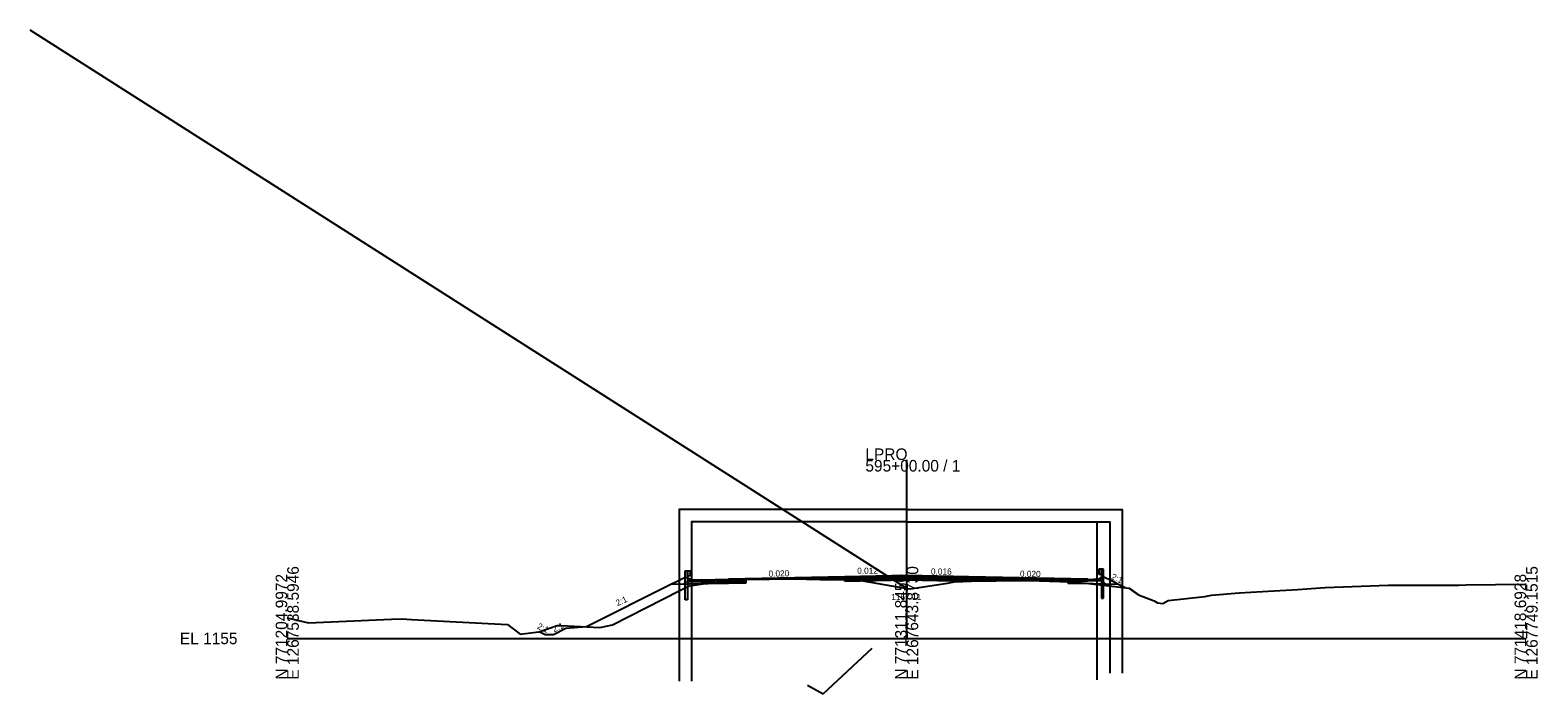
# Model space of a CAD drawing. Extents: x -3833 to 1267678, y -522 to 773248.
# Drawn here: x -62.2 to 302.8, y 5986.6 to 6147.2 of the extents above; entities that cross this region are included whole.
import ezdxf

# ---------------------------------------------------------------- set-up
doc = ezdxf.new("R2010")
doc.units = 0
for name, color, linetype in [('Exist Cross Section Cell', 7, 'Continuous'), ('Exist XS Center Line Elevation Label', 7, 'Continuous'), ('Exist XS Ground Line', 7, 'Continuous'), ('Prop CMT DNC', 7, 'Continuous'), ('Prop CMT Guardrail Graphics', 7, 'Continuous'), ('Prop CMT Pvmt Course 1', 7, 'Continuous'), ('Prop CMT Pvmt Course 2', 7, 'Continuous'), ('Prop CMT Pvmt Course 4', 7, 'Continuous'), ('Prop CMT Shld Paved Course 1', 7, 'Continuous'), ('Prop CMT Shld Paved Course 2', 7, 'Continuous'), ('Prop CMT Shld Paved Course 4', 7, 'Continuous'), ('Prop CMT Slope Grass', 7, 'Continuous'), ('Prop CMT Subgrade Earthwork', 7, 'Continuous'), ('Prop Corridor Mesh Bottom', 7, 'Continuous'), ('Prop XS Ditch Slope Text', 7, 'Continuous'), ('Prop XS Finish Grade', 7, 'Continuous'), ('Prop XS Label Text', 7, 'Continuous'), ('Prop XS SE Text', 7, 'Continuous'), ('Scratch_Level_1', 7, 'Continuous'), ('Scratch_Level_5', 7, 'Continuous'), ('Typical Curb CELL', 7, 'Continuous')]:
    doc.layers.add(name, color=color, linetype=linetype)

msp = doc.modelspace()

# ---------------------------------------------------------------- linework, layer by layer
at = {"layer": 'Exist Cross Section Cell'}
for p, q in [((150, 6000), (150, 6043.17)), ((0, 6000), (150, 6000)), ((150, 6000), (300, 6000))]:
    msp.add_line(p, q, dxfattribs=at)
at = {"layer": 'Exist XS Ground Line'}
for p, q in [((97.99, 6012.77), (106.25, 6013.98)), ((106.25, 6013.98), (108.66, 6014.13)), ((108.66, 6014.13), (111.05, 6014.3)), ((108.66, 6014.13), (111.05, 6014.3)), ((111.05, 6014.3), (116.77, 6014.34)), ((111.05, 6014.3), (116.77, 6014.34)), ((116.77, 6014.34), (122.39, 6014.39)), ((116.77, 6014.34), (122.39, 6014.39)), ((122.39, 6014.39), (129.02, 6014.27)), ((122.39, 6014.39), (129.02, 6014.27)), ((129.02, 6014.27), (136.17, 6014.14)), ((129.02, 6014.27), (136.17, 6014.14)), ((136.17, 6014.14), (137.39, 6014.09)), ((136.17, 6014.14), (137.39, 6014.09)), ((137.39, 6014.09), (138.63, 6014.02)), ((137.39, 6014.09), (138.63, 6014.02)), ((138.63, 6014.02), (139.36, 6013.96)), ((138.63, 6014.02), (139.36, 6013.96)), ((139.36, 6013.96), (150, 6012.11)), ((139.36, 6013.96), (150, 6012.11)), ((150.83, 6011.96), (159.85, 6013.35)), ((150.83, 6011.96), (159.85, 6013.35)), ((159.85, 6013.35), (160.7, 6013.49)), ((159.85, 6013.35), (160.7, 6013.49)), ((160.7, 6013.49), (161.61, 6013.67)), ((160.7, 6013.49), (161.61, 6013.67)), ((161.61, 6013.67), (165.61, 6013.84)), ((161.61, 6013.67), (165.61, 6013.84)), ((165.61, 6013.84), (177.73, 6014.03)), ((165.61, 6013.84), (177.73, 6014.03)), ((177.73, 6014.03), (179.64, 6013.98)), ((177.73, 6014.03), (179.64, 6013.98)), ((179.64, 6013.98), (189.48, 6013.71)), ((179.64, 6013.98), (189.48, 6013.71)), ((189.48, 6013.71), (193.42, 6013.4)), ((193.42, 6013.4), (203.88, 6012.13)), ((193.42, 6013.4), (203.88, 6012.13)), ((285.5, 6012.96), (292.56, 6013.03)), ((292.56, 6013.03), (300, 6013.08)), ((78.73, 6003.26), (95.07, 6011.55)), ((78.73, 6003.26), (95.07, 6011.55)), ((95.07, 6011.55), (97.16, 6012.67)), ((95.07, 6011.55), (97.16, 6012.67)), ((97.16, 6012.67), (97.99, 6012.77)), ((150, 6012.11), (150.83, 6011.96)), ((150, 6012.11), (150.83, 6011.96)), ((203.87, 6012.09), (206.15, 6010.47)), ((203.88, 6012.13), (206.16, 6010.51)), ((206.16, 6010.51), (209.91, 6009.06)), ((206.16, 6010.51), (209.91, 6009.06)), ((213.31, 6009.13), (222.19, 6010.14)), ((213.31, 6009.13), (222.19, 6010.14)), ((222.19, 6010.14), (223.85, 6010.44)), ((222.19, 6010.14), (223.85, 6010.44)), ((223.85, 6010.44), (230.49, 6011.04)), ((223.85, 6010.44), (230.49, 6011.04)), ((230.49, 6011.04), (244.64, 6011.79)), ((230.49, 6011.04), (244.64, 6011.79)), ((244.64, 6011.79), (251.33, 6012.28)), ((244.64, 6011.79), (251.33, 6012.28)), ((251.33, 6012.28), (266.61, 6012.88)), ((266.61, 6012.88), (283.6, 6012.88)), ((283.6, 6012.88), (285.5, 6012.96)), ((209.91, 6009.06), (210.72, 6008.63)), ((209.91, 6009.06), (210.72, 6008.63)), ((210.72, 6008.63), (211.99, 6008.42)), ((210.72, 6008.63), (211.99, 6008.42)), ((211.99, 6008.42), (213.31, 6009.13)), ((211.99, 6008.42), (213.31, 6009.13)), ((0, 6004.94), (5.16, 6003.79)), ((5.16, 6003.79), (25.23, 6004.67)), ((25.23, 6004.67), (27.81, 6004.76)), ((27.81, 6004.76), (30.1, 6004.6)), ((30.1, 6004.6), (53.33, 6003.38)), ((53.33, 6003.38), (56.43, 6001.03)), ((53.33, 6003.38), (56.43, 6001.03)), ((60.91, 6001.55), (65.38, 6003.09)), ((60.91, 6001.55), (65.38, 6003.09)), ((65.38, 6003.09), (66.32, 6003.13)), ((65.38, 6003.09), (66.32, 6003.13)), ((66.32, 6003.13), (75.69, 6002.6)), ((66.32, 6003.13), (75.69, 6002.6)), ((75.69, 6002.6), (78.73, 6003.26)), ((75.69, 6002.6), (78.73, 6003.26)), ((56.43, 6001.03), (60.91, 6001.55)), ((56.43, 6001.03), (60.91, 6001.55))]:
    msp.add_line(p, q, dxfattribs=at)
at = {"layer": 'Prop CMT Guardrail Graphics'}
for p, q in [((196.53, 6016.73), (196.53, 6015.54)), ((197.2, 6016.73), (196.53, 6016.73)), ((197.2, 6016.73), (197.2, 6014.21)), ((197.68, 6016.73), (197.2, 6016.73)), ((197.2, 6015.54), (197.2, 6016.73)), ((197.68, 6014.22), (197.68, 6016.73)), ((96.4, 6013.85), (96.4, 6016.35)), ((96.4, 6016.35), (96.89, 6016.35)), ((96.4, 6009.34), (96.4, 6013.85)), ((96.89, 6016.35), (96.89, 6013.84)), ((96.89, 6015.17), (96.89, 6016.35)), ((96.89, 6016.35), (97.55, 6016.35)), ((97.55, 6015.17), (96.89, 6015.17)), ((96.89, 6013.84), (96.89, 6009.34)), ((97.55, 6016.35), (97.55, 6015.17)), ((97.55, 6016.27), (97.55, 6015.25)), ((97.65, 6016.25), (97.55, 6016.27)), ((97.55, 6015.25), (97.65, 6015.27)), ((97.57, 6015.8), (97.8, 6016)), ((97.57, 6015.71), (97.57, 6015.8)), ((97.8, 6015.51), (97.57, 6015.71)), ((97.8, 6016.15), (97.65, 6016.25)), ((97.65, 6015.27), (97.8, 6015.37)), ((97.8, 6016), (97.8, 6016.15)), ((97.8, 6015.37), (97.8, 6015.51)), ((196.29, 6016.52), (196.43, 6016.62)), ((196.29, 6016.38), (196.29, 6016.52)), ((196.52, 6016.18), (196.29, 6016.38)), ((196.29, 6015.89), (196.52, 6016.09)), ((196.29, 6015.74), (196.29, 6015.89)), ((196.43, 6015.64), (196.29, 6015.74)), ((196.43, 6016.62), (196.53, 6016.65)), ((196.53, 6015.62), (196.43, 6015.64)), ((196.52, 6016.09), (196.52, 6016.18)), ((196.53, 6016.65), (196.53, 6015.62)), ((196.53, 6015.54), (197.2, 6015.54)), ((197.2, 6014.21), (197.2, 6009.71)), ((197.68, 6009.71), (197.68, 6014.22)), ((197.2, 6009.71), (197.68, 6009.71)), ((96.89, 6009.34), (96.4, 6009.34))]:
    msp.add_line(p, q, dxfattribs=at)
at = {"layer": 'Prop CMT Pvmt Course 1'}
for p, q in [((135, 6014.9), (106.89, 6014.34)), ((106.89, 6014.34), (106.89, 6014.34)), ((106.89, 6014.34), (106.89, 6014.09)), ((106.89, 6014.09), (111.05, 6014.17)), ((106.89, 6014.09), (106.89, 6014.09)), ((111.05, 6014.3), (135, 6014.65)), ((135, 6014.65), (135, 6014.9)), ((135, 6014.65), (135, 6014.65)), ((193.84, 6014.32), (165, 6014.9)), ((165, 6014.9), (165, 6014.65)), ((165, 6014.65), (165, 6014.65)), ((165, 6014.65), (193.84, 6014.07)), ((189, 6014.17), (189, 6014.42)), ((189, 6014.42), (193.84, 6014.32)), ((195.16, 6014.01), (195.16, 6014.01))]:
    msp.add_line(p, q, dxfattribs=at)
at = {"layer": 'Prop CMT Pvmt Course 2'}
for p, q in [((150, 6014.95), (135, 6014.65)), ((135, 6014.65), (135, 6014.65)), ((135, 6014.65), (135, 6014.32)), ((135, 6014.32), (150, 6014.62)), ((135, 6014.32), (135, 6014.32)), ((135, 6014.32), (135, 6014.32)), ((135, 6014.32), (135, 6014.32)), ((165, 6014.65), (150, 6014.95)), ((150, 6014.62), (165, 6014.32)), ((165, 6014.32), (165, 6014.65)), ((165, 6014.65), (165, 6014.65)), ((165, 6014.32), (165, 6014.32)), ((165, 6014.32), (165, 6014.32)), ((165, 6014.32), (165, 6014.32))]:
    msp.add_line(p, q, dxfattribs=at)
at = {"layer": 'Prop CMT Pvmt Course 4'}
for p, q in [((135, 6014.32), (130.86, 6014.23)), ((130.86, 6014.23), (130.95, 6014.24)), ((130.86, 6014.23), (130.86, 6014.23)), ((130.95, 6014.24), (135, 6014.16)), ((150, 6014.62), (135, 6014.32)), ((135, 6014.16), (135, 6014.32)), ((135, 6014.32), (135, 6014.32)), ((135, 6014.32), (135, 6014.32)), ((135, 6014.32), (135, 6014.32)), ((135, 6014.32), (135, 6014.32)), ((135, 6014.32), (135.01, 6013.87)), ((135, 6014.16), (135, 6014.16)), ((135, 6014.16), (135, 6014.16)), ((135, 6014.16), (135, 6014.16)), ((135.01, 6013.86), (150, 6014.16)), ((135.01, 6013.87), (135.01, 6013.87)), ((135.01, 6013.87), (135.01, 6013.86)), ((135.01, 6013.86), (135.01, 6013.86)), ((135.01, 6013.86), (135.01, 6013.86)), ((165, 6014.32), (150, 6014.62)), ((150, 6014.16), (165, 6013.86)), ((165, 6013.86), (165, 6014.32)), ((165, 6014.32), (165, 6014.32)), ((165, 6014.32), (165, 6014.32)), ((165, 6013.81), (165, 6014.32)), ((165, 6014.32), (165, 6014.32)), ((165, 6014.32), (165, 6014.32)), ((165, 6013.86), (165, 6013.86)), ((165, 6013.86), (165, 6013.86)), ((165, 6013.86), (165, 6013.86)), ((165.61, 6013.84), (165, 6013.81)), ((165, 6013.81), (165, 6013.81)), ((165, 6013.81), (165, 6013.81)), ((165, 6013.81), (165, 6013.81)), ((166.15, 6013.85), (165.61, 6013.84)), ((173.29, 6013.96), (166.15, 6013.85)), ((177.73, 6014.03), (173.29, 6013.96)), ((179.44, 6013.99), (177.73, 6014.03)), ((182.31, 6013.91), (179.44, 6013.99)), ((187.82, 6013.76), (182.31, 6013.91)), ((189, 6013.73), (187.82, 6013.76)), ((189, 6013.84), (189, 6013.73))]:
    msp.add_line(p, q, dxfattribs=at)
at = {"layer": 'Prop CMT Shld Paved Course 1'}
for p, q in [((97.63, 6013.87), (97.63, 6013.87)), ((97.63, 6013.87), (97.63, 6013.87)), ((97.63, 6013.87), (97.63, 6013.87)), ((97.63, 6013.87), (97.63, 6013.87)), ((97.89, 6014.12), (97.89, 6014.12)), ((97.89, 6014.12), (97.89, 6014.12)), ((100.22, 6014.2), (106.89, 6014.34)), ((106.89, 6014.09), (100.22, 6013.95)), ((106.89, 6014.34), (106.89, 6014.09)), ((106.89, 6014.09), (106.89, 6014.09)), ((150, 6015.2), (135, 6014.9)), ((135, 6014.65), (150, 6014.95)), ((135, 6014.9), (135, 6014.9)), ((135, 6014.9), (135, 6014.65)), ((135, 6014.65), (135, 6014.65)), ((135, 6014.65), (135, 6014.65)), ((165, 6014.9), (150, 6015.2)), ((150, 6014.95), (165, 6014.65)), ((165, 6014.65), (165, 6014.9)), ((165, 6014.9), (165, 6014.9)), ((165, 6014.65), (165, 6014.65)), ((165, 6014.65), (165, 6014.65)), ((189, 6014.17), (189, 6014.17)), ((189, 6014.17), (193.84, 6014.07)), ((196.16, 6014.24), (195.16, 6014.26))]:
    msp.add_line(p, q, dxfattribs=at)
at = {"layer": 'Prop CMT Shld Paved Course 2'}
for p, q in [((97.29, 6013.53), (97.29, 6013.53)), ((97.29, 6013.53), (97.29, 6013.53)), ((97.29, 6013.53), (97.29, 6013.53)), ((97.29, 6013.53), (97.29, 6013.53)), ((97.63, 6013.87), (97.63, 6013.87)), ((97.63, 6013.87), (97.63, 6013.87)), ((106.89, 6014.09), (106.89, 6013.75)), ((106.89, 6013.75), (106.89, 6013.75)), ((111.05, 6014.3), (120.07, 6014.43)), ((111.05, 6014.3), (111.05, 6014.3)), ((120.07, 6014.43), (128.15, 6014.54)), ((129.02, 6014.27), (122.39, 6014.39)), ((128.15, 6014.54), (128.65, 6014.56)), ((128.65, 6014.56), (129.85, 6014.57)), ((130.86, 6014.23), (129.02, 6014.27)), ((129.02, 6014.27), (129.02, 6014.27)), ((129.85, 6014.57), (135, 6014.65)), ((135, 6014.32), (130.86, 6014.23)), ((130.86, 6014.23), (130.86, 6014.23)), ((135, 6014.65), (135, 6014.65)), ((135, 6014.65), (135, 6014.32)), ((135, 6014.32), (135, 6014.32)), ((135, 6014.32), (135, 6014.32)), ((165, 6014.32), (165, 6014.65)), ((165, 6014.65), (165, 6014.65)), ((165, 6014.65), (165.61, 6014.64)), ((165.61, 6014.3), (165, 6014.32)), ((165, 6014.32), (165, 6014.32)), ((165, 6014.32), (165, 6014.32)), ((165.61, 6014.64), (165.86, 6014.63)), ((165.86, 6014.3), (165.61, 6014.3)), ((165.86, 6014.63), (165.86, 6014.63)), ((165.86, 6014.63), (177.73, 6014.4)), ((177.73, 6014.06), (165.86, 6014.3)), ((165.86, 6014.3), (165.86, 6014.3)), ((177.73, 6014.4), (177.73, 6014.4)), ((177.73, 6014.4), (179.64, 6014.36)), ((179.64, 6014.02), (177.73, 6014.06)), ((177.73, 6014.06), (177.73, 6014.06)), ((179.64, 6014.36), (189, 6014.17)), ((179.64, 6014.36), (179.64, 6014.36)), ((189, 6013.84), (179.64, 6014.02)), ((179.64, 6014.02), (179.64, 6014.02)), ((189, 6014.17), (189, 6013.84))]:
    msp.add_line(p, q, dxfattribs=at)
at = {"layer": 'Prop CMT Shld Paved Course 4'}
for p, q in [((95.98, 6013.08), (96.69, 6013.79)), ((96.69, 6013.79), (97.2, 6013.79)), ((106.89, 6013.3), (96.82, 6013.09)), ((100.22, 6013.62), (111.05, 6013.84)), ((100.22, 6013.79), (100.22, 6013.62)), ((106.89, 6013.75), (106.89, 6013.3)), ((193.83, 6013.74), (189, 6013.84)), ((193.83, 6013.91), (193.83, 6013.74)), ((197.36, 6013.91), (196.85, 6013.91)), ((198.06, 6013.2), (197.36, 6013.91))]:
    msp.add_line(p, q, dxfattribs=at)
at = {"layer": 'Prop CMT Slope Grass'}
for p, q in [((94.59, 6013.86), (92.91, 6013.02)), ((96.5, 6014.81), (94.59, 6013.86)), ((96.5, 6014.81), (97.2, 6014.46)), ((197.61, 6014.96), (196.85, 6014.58)), ((197.61, 6014.96), (199.6, 6013.97)), ((199.6, 6013.97), (201.27, 6013.14))]:
    msp.add_line(p, q, dxfattribs=at)
at = {"layer": 'Prop CMT Subgrade Earthwork'}
for p, q in [((111.05, 6013.38), (92.91, 6013.02)), ((111.05, 6014.3), (111.05, 6013.38)), ((135.01, 6013.86), (135, 6014.16)), ((150, 6014.16), (135.01, 6013.86)), ((165, 6013.86), (150, 6014.16)), ((165, 6013.81), (165, 6013.86)), ((189, 6013.73), (189, 6013.38)), ((189, 6013.38), (195.17, 6013.26)), ((195.17, 6013.26), (201.27, 6013.14))]:
    msp.add_line(p, q, dxfattribs=at)
at = {"layer": 'Prop Corridor Mesh Bottom'}
for p, q in [((135, 6014.9), (135, 6014.65)), ((165, 6014.9), (165, 6014.65))]:
    msp.add_line(p, q, dxfattribs=at)
at = {"layer": 'Prop XS Finish Grade'}
for p, q in [((92.91, 6013.02), (72.44, 6002.78)), ((201.27, 6013.14), (203.09, 6012.23))]:
    msp.add_line(p, q, dxfattribs=at)
msp.add_lwpolyline([(72.44, 6002.78), (67.44, 6002.37), (64.44, 6000.87), (62.44, 6000.87), (61, 6001.59)], dxfattribs=at)
at = {"layer": 'Scratch_Level_1'}
msp.add_line((150, 6012.11), (-62.25, 6147.17), dxfattribs=at)
at = {"layer": 'Scratch_Level_5'}
for p, q in [((129.76, 5986.58), (141.61, 5997.61)), ((125.97, 5988.69), (129.76, 5986.58))]:
    msp.add_line(p, q, dxfattribs=at)
for points in [[(150, 6031.19), (94.89, 6031.19), (94.89, 5989.68)], [(150, 6028.19), (97.89, 6028.19), (97.89, 5989.68)], [(150, 6031.19), (202.17, 6031.19), (202.17, 5991.57)], [(150, 6028.19), (196.05, 6028.19), (196.05, 5990)], [(150, 6028.19), (199.17, 6028.19), (199.17, 5991.57)]]:
    msp.add_lwpolyline(points, dxfattribs=at)
at = {"layer": 'Typical Curb CELL'}
for p, q in [((97.2, 6013.79), (97.2, 6014.46)), ((97.89, 6014.12), (97.2, 6014.46)), ((97.2, 6013.79), (100.22, 6013.79)), ((97.23, 6014.09), (97.39, 6014.13)), ((97.37, 6014.04), (97.23, 6014.09)), ((97.39, 6014.13), (97.37, 6014.04)), ((97.9, 6014), (97.8, 6013.93)), ((97.8, 6013.93), (97.97, 6013.89)), ((100.21, 6014.2), (97.89, 6014.12)), ((97.97, 6013.89), (97.9, 6014)), ((98.65, 6014.06), (98.61, 6013.95)), ((98.61, 6013.95), (98.73, 6013.94)), ((98.73, 6013.94), (98.65, 6014.06)), ((99.15, 6014), (99.05, 6013.93)), ((99.05, 6013.93), (99.22, 6013.89)), ((99.22, 6013.89), (99.15, 6014)), ((99.89, 6014.06), (99.86, 6013.95)), ((99.86, 6013.95), (99.98, 6013.94)), ((99.98, 6013.94), (99.89, 6014.06)), ((100.22, 6014.2), (100.22, 6014.2)), ((100.22, 6013.79), (100.22, 6014.19)), ((193.83, 6014.32), (193.83, 6014.32)), ((193.83, 6013.91), (193.83, 6014.31)), ((196.85, 6013.91), (193.83, 6013.91)), ((193.84, 6014.32), (196.16, 6014.24)), ((194.07, 6014.06), (194.15, 6014.18)), ((194.19, 6014.07), (194.07, 6014.06)), ((194.15, 6014.18), (194.19, 6014.07)), ((194.83, 6014.01), (194.9, 6014.12)), ((195, 6014.05), (194.83, 6014.01)), ((194.9, 6014.12), (195, 6014.05)), ((195.32, 6014.06), (195.4, 6014.18)), ((195.44, 6014.07), (195.32, 6014.06)), ((195.4, 6014.18), (195.44, 6014.07)), ((196.08, 6014.01), (196.14, 6014.12)), ((196.25, 6014.05), (196.08, 6014.01)), ((196.14, 6014.12), (196.25, 6014.05)), ((196.16, 6014.24), (196.85, 6014.58)), ((196.66, 6014.25), (196.68, 6014.16)), ((196.81, 6014.21), (196.66, 6014.25)), ((196.68, 6014.16), (196.81, 6014.21)), ((196.85, 6013.91), (196.85, 6014.58))]:
    msp.add_line(p, q, dxfattribs=at)
for centre in [(97.26, 6014.17), (97.36, 6013.9), (97.48, 6013.95), (97.74, 6013.98), (97.75, 6013.93), (97.93, 6013.84), (97.96, 6013.94), (98.15, 6013.9), (98.2, 6014.02), (98.33, 6013.99), (98.36, 6013.86), (98.41, 6013.9), (98.61, 6013.9), (98.73, 6013.95), (98.82, 6013.94), (98.92, 6013.89), (98.98, 6014.04), (98.99, 6013.98), (99, 6013.93), (99.21, 6013.94), (99.4, 6013.9), (99.45, 6014.02), (99.5, 6013.99), (99.57, 6013.99), (99.61, 6013.86), (99.66, 6013.9), (99.72, 6014.08), (100.09, 6014.15), (100.13, 6014.03), (193.92, 6014.15), (193.96, 6014.27), (194.33, 6014.2), (194.38, 6014.02), (194.44, 6013.98), (194.47, 6014.11), (194.55, 6014.11), (194.6, 6014.14), (194.65, 6014.02), (194.84, 6014.06), (195.05, 6014.05), (195.06, 6014.1), (195.07, 6014.16), (195.13, 6014.01), (195.23, 6014.06), (195.32, 6014.07), (195.44, 6014.02), (195.63, 6014.02), (195.69, 6013.98), (195.72, 6014.11), (195.85, 6014.14), (195.9, 6014.02), (196.09, 6014.06), (196.12, 6013.96), (196.29, 6014.05), (196.31, 6014.1), (196.57, 6014.07), (196.69, 6014.02), (196.79, 6014.29)]:
    msp.add_circle(centre, 0.00802, dxfattribs=at)
for centre, start, end in [((100.21, 6014.19), 0, 92.048), ((193.84, 6014.31), 87.952, 180)]:
    msp.add_arc(centre, 0.0104, start, end, dxfattribs=at)

# ---------------------------------------------------------------- texts
at = {"layer": 'Exist Cross Section Cell'}
for s, p in [('LPRO', (140, 6043.17)), ('595+00.00 / 1', (140, 6040.37)), ('EL 1155', (-26, 5998.6))]:
    msp.add_text(s, height=2.8, dxfattribs=at).set_placement(p)
for s, p in [('E 1267538.5946', (2.8, 5990)), ('E 1267643.8730', (152.8, 5990)), ('E 1267749.1515', (302.8, 5990)), ('N 771204.9972', (0, 5990)), ('N 771311.8450', (150, 5990)), ('N 771418.6928', (300, 5990))]:
    msp.add_text(s, height=2.8, rotation=90, dxfattribs=at).set_placement(p)
at = {"layer": 'Exist XS Center Line Elevation Label'}
msp.add_text('1167.11', height=1.5, dxfattribs=at).set_placement((146.29, 6009.27))
at = {"layer": 'Prop CMT DNC'}
for p in [(101.99, 6014.24), (111, 6014.42), (111, 6014.42), (135, 6014.9), (135, 6014.9), (150, 6015.2), (165, 6014.9), (165, 6014.9), (189, 6014.42), (193, 6014.34), (195.92, 6014.24), (221.07, 6010.01), (73.12, 6002.75)]:
    msp.add_text('X', height=0.00025, dxfattribs=at).set_placement(p)
at = {"layer": 'Prop XS Ditch Slope Text'}
msp.add_text('2:1', height=1.5, rotation=335.81, dxfattribs=at).set_placement((199.4, 6014.39))
at = {"layer": 'Prop XS Label Text'}
for rotation, p in [(24.9367, (79.97, 6007.77)), (335.0633, (60.38, 6002.43)), (24.9367, (64.62, 6001.42))]:
    msp.add_text('2:1', height=1.5, rotation=rotation, dxfattribs=at).set_placement(p)
at = {"layer": 'Prop XS SE Text'}
for s, rotation, p in [('0.012', 0.2693, (138.02, 6015.61)), ('0.016', 0.0826, (155.88, 6015.42)), ('0.020', 1.397, (116.57, 6014.9)), ('0.020', 358.8542, (177.41, 6014.92))]:
    msp.add_text(s, height=1.5, rotation=rotation, dxfattribs=at).set_placement(p)

doc.saveas('drawing.dxf')
